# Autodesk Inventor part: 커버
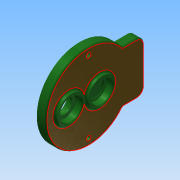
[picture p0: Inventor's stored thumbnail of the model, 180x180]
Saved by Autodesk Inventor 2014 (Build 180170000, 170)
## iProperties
Created: 2016-02
Part Number: 커버
Material: 알루미늄 6061
Document SubType Name: Modeling
Designer: mduedu
Density: 2.71 g/cm^3
Mass: 157.248 g
Surface Area: 178.476 cm^2
Volume: 58.0252 cm^3
Appearance: 매끄러움 - 짙은 산림 녹색
Author: mduedu
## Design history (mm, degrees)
sketch "스케치1"
  geometry: C1 r 43 at (0, 0); 1 further point
  constraints: 1 centre point, 1 coincident
  dimensions: "d0" = 86 diameter of C1
extrude "돌출1" new body sketch "스케치1" distance "d1" = 9; taper "d2" = 0 deg
sketch "스케치2"
  geometry: C1 r 14 at (0, 11); 1 further point
  constraints: 1 centre point, 1 vertical alignment
  dimensions: "d3" = 28 diameter of C1; "d6" = 11 distance of C1.centre point (0, 0)
extrude "돌출2" join sketch "스케치2" distance "d7" = 3; taper "d8" = 0 deg
sketch "스케치3"
  geometry: C1 r 14 at (0, -20); 1 further point
  constraints: 1 centre point, 1 vertical alignment
  dimensions: "d9" = 28 diameter of C1; "d10" = 20 distance of C1.centre point (0, 0)
extrude "돌출3" join sketch "스케치3" distance "d11" = 3; taper "d12" = 0 deg
hole "구멍1" diameter "d15" = 22; stored, may be unused: countersink angle "d19" = 90 deg, drill point angle "d21" = 0 deg; dims "d13" = 10, "d14" = 10, "d16" = 6, "d17" = 4, "d18" = 2, "d20" = 7
hole "구멍2" diameter "d24" = 18; stored, may be unused: countersink angle "d28" = 90 deg, drill point angle "d30" = 0 deg; dims "d22" = 10, "d23" = 10, "d25" = 6, "d26" = 4, "d27" = 2, "d29" = 1
hole "구멍3" diameter "d33" = 22; stored, may be unused: countersink angle "d37" = 90 deg, drill point angle "d39" = 0 deg; dims "d34" = 6, "d35" = 4, "d36" = 2, "d38" = 7, "d73" = 10, "d74" = 10
sketch "스케치7"
  geometry: L1 (-26, 34.249)-(26, 34.249); L2 (26, 34.249)-(26, 56); L3 (26, 56)-(-26, 56); L4 (-26, 56)-(-26, 34.249); A1 r 43 centre (0, 0) between (-26, 34.249) and (26, 34.249) reference; 1 further point
  constraints: 8 end point, 2 parallel, 2 point on circle, 1 horizontal, 1 perpendicular
  dimensions: "d95" = 52 distance of L2.end L3.end; "d97" = 56 distance from line of L3 point (0, 0)
extrude "돌출5" join sketch "스케치7" stored distance "d98" = 10; taper "d99" = 0 deg
sketch "스케치4"
  geometry: C1 r 14 at (0, -20) reference; C2 r 18 at (0, -20); 1 further point
  constraints: 1 centre point, 1 coincident
  dimensions: "d40" = 36 diameter of C2
extrude "돌출4" join sketch "스케치4" distance "d41" = 4; taper "d42" = 0 deg
hole "구멍4" diameter "d45" = 22; stored, may be unused: countersink angle "d49" = 90 deg, drill point angle "d51" = 0 deg; dims "d43" = 10, "d44" = 10, "d46" = 6, "d47" = 4, "d48" = 2, "d50" = 7
hole "구멍5" diameter "d54" = 15; stored, may be unused: countersink angle "d58" = 90 deg, drill point angle "d60" = 0 deg; dims "d52" = 10, "d53" = 10, "d55" = 6, "d56" = 4, "d57" = 2, "d59" = 7
fillet "모깎기1" dims "d61" = 0.3
fillet "모깎기2" dims "d62" = 2
chamfer "모따기1" distance "d63" = 1; stored, may be unused: second distance "d64" = 2, angle "d65" = 45 deg
fillet "모깎기6" dims "d88" = 2
sketch "스케치5" dims "d67" = 72
  geometry: 4 further points
  constraints: 2 horizontal alignment, 1 coincident, 5 other
  dimensions: "d71" = 360 deg dimension on point (0, 0) point (-36, 0) (derived)
fillet "모깎기4" dims "d75" = 2
sketch "스케치6"
  geometry: 2 further points
hole "구멍6" sketch "스케치6" at (36, 0), (-36, 0) diameter "d76" = 4.5; stored, may be unused: countersink angle "d80" = 90 deg, drill point angle "d82" = 0 deg; dims "d77" = 6, "d78" = 8, "d79" = 4.6, "d81" = 8
fillet "모깎기7" dims "d100" = 8, "d101" = 2
chamfer "모따기2" distance "d90" = 1; stored, may be unused: second distance "d91" = 2, angle "d92" = 45 deg
node "솔리드1"
node "절단 모서리 투영1"
